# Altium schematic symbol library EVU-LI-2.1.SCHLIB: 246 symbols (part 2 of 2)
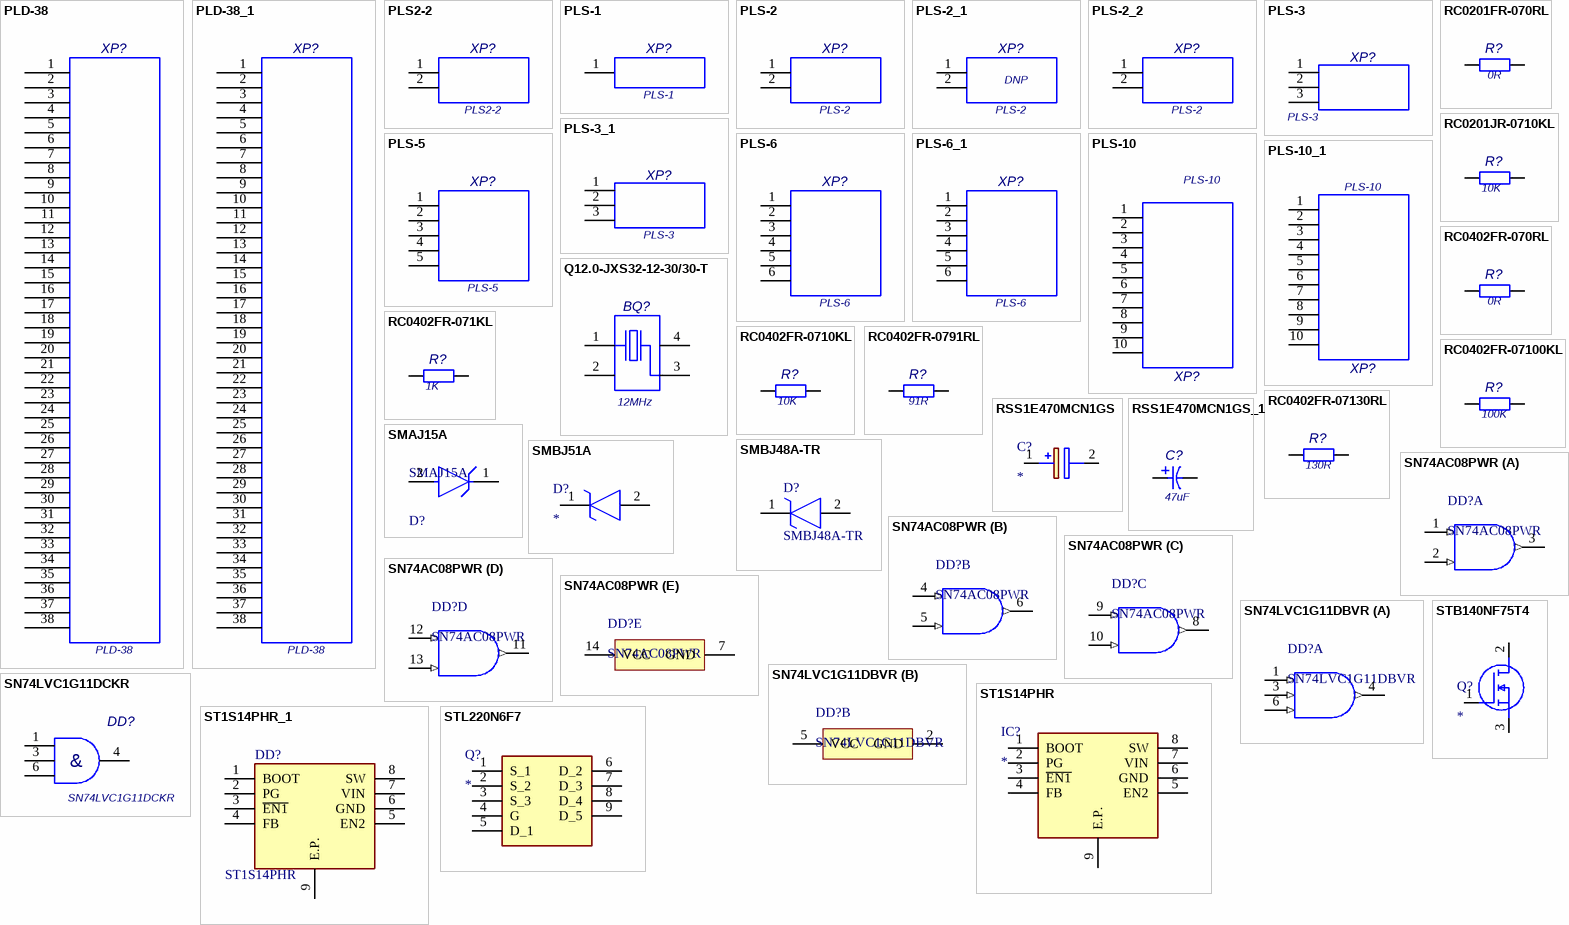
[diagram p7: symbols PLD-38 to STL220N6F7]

## PLS-10
designator XP?
2.54 pitch, 1 rows, 8.54 height; Manufacturer: "ТД Бурый медведь"
footprint PLS10-254PX254X25X854N
pins: 1, 2, 3, 4, 5, 6, 7, 8, 9, 10

## PLS-10_1
designator XP?, comment PLS-10
2.54 pitch, 1 rows, 8.54 height; Manufacturer: "ТД Бурый медведь"
footprint PLS10-254PX254X25X854N
pins: 1, 2, 3, 4, 5, 6, 7, 8, 9, 10

## Q12.0-JXS32-12-30/30-T
designator BQ?  value 12MHz  (hidden comment: Q12.0-JXS32-12-30/30-T)
Quartz Crystal 12MHz; Manufacturer: "Jauch"; ManufacturerPartNumber: Q12.0-JXS32-12-30/30-T1; MARK: ASFLK; Value Ru: 12,000 МГц
footprint JXS32X330X270X70N
pins: 1, 2, 3, 4

## RC0201FR-070RL
designator R?  value 0R  (hidden comment: RC0201FR-070RL)
0201 0 Ohm ±1% 0.05 W; Manufacturer: "Yageo"; Power_Voltage: 0,05 W; MARK: 000; TKE: 0402; NOM: 0402 0R ±1% 0,05 W; Value Ru: 0 Ом
footprint RES0201 (SMD Chip Resistor 0201,  metric 0603)
pins: 1, 2

## RC0201JR-0710KL
designator R?  value 10K  (hidden comment: RC0201JR-0710KL)
0201 10 kOhm ± 5% 0.05W; Manufacturer: "Yageo"; Power_Voltage: 0,05 W; MARK: 103; TKE: 0201; NOM: 0201 10K ±5% 0,05 W; Value Ru: 10 кОм
footprint RES0201 (SMD Chip Resistor 0201,  metric 0603)
pins: 1, 2

## RC0402FR-070RL
designator R?  value 0R  (hidden comment: RC0402FR-070RL)
0402 0 Ohm ±1% 0.063W; Manufacturer: "Yageo"; Power_Voltage: 0,0625 W; MARK: 000; TKE: 0402; NOM: 0402 0R ±1% 0,0625 W; Value Ru: 0 Ом
footprint RESC1005X35N
pins: 1, 2

## RC0402FR-071KL
designator R?  value 1K  (hidden comment: RC0402FR-071KL)
0402 1 kOhm ±1% 0.063W; Manufacturer: "Yageo"; Power_Voltage: 0,0625 W; MARK: 102; TKE: 0402; NOM: 0402 1K ±1% 0,0625 W; Value Ru: 1 кОм
footprint RESC1005X35N
pins: 1, 2

## RC0402FR-0710KL
designator R?  value 10K  (hidden comment: RC0402FR-0710KL)
0402 10 kOhm ±1% 0.063W; Manufacturer: "Yageo"; Power_Voltage: 0,0625 W; MARK: 103; TKE: 0402; NOM: 0402 10K ±1% 0,0625 W; Value Ru: 10 кОм
footprint RESC1005X35N
pins: 1, 2

## RC0402FR-0791RL
designator R?  value 91R  (hidden comment: RC0402FR-0791RL)
0402 91 Ohm ±1% 0.063W; Manufacturer: "Yageo"; Power_Voltage: 0,0625 W; MARK: 102; TKE: 0402; NOM: 0402 91R ±1% 0,0625 W; Value Ru: 91 Ом
footprint RESC1005X35N
pins: 1, 2

## RC0402FR-07100KL
designator R?  value 100K  (hidden comment: RC0402FR-07100KL)
0402 100 kOhm ±1% 0.063W; Manufacturer: "Yageo"; Power_Voltage: 0,0625 W; MARK: 103; TKE: 0402; NOM: 0402 100K ±1% 0,0625 W; Value Ru: 100 кОм
footprint RESC1005X35N
pins: 1, 2

## RC0402FR-07130RL
designator R?  value 130R  (hidden comment: RC0402FR-07130RL)
0402 130 Ohm ±1% 0.063W; Manufacturer: "Yageo"; Power_Voltage: 0,0625 W; MARK: 102; TKE: 0402; NOM: 0402 130R ±1% 0,0625 W; Value Ru: 130 Ом
footprint RESC1005X35N
pins: 1, 2

## RSS1E470MCN1GS
designator C?
Capacitor Polarised; Manufacturer_Name: Nichicon; Manufacturer_Part_Number: RSS1E470MCN1GS
footprint CAPAE650X600N
pins: 1 +, 2 -

## RSS1E470MCN1GS_1
designator C?, comment value 47uF  (hidden comment: RSS1E470MCN1GS)
47uF±20% 25V; Manufacturer: "Nichicon"; Tolerance: ±20%; Value Ru: 47 мкФ
footprint CAPAE650X600N
pins: 1, 2

## SMAJ15A
designator D?
TVS DIODE 15V 24.4V SMA; Manufacturer: "Bourns Inc."; Max Junction Temp: +150°C; Peak Pulse Current: 16.4A; Direction: Unidirectional; Breakdown Voltage: 16.7V; Number Of Channels: 1; Peak Pulse Power: 400W; TKE: SMA (DO-214AC)
footprint FP-SMA-MFG
pins: 1 C, 2 A

## SMBJ48A-TR
designator D?
TVS Diode (Uni-directional); Manufacturer_Name: STMicroelectronics; Manufacturer: "STMicroelectronics"; Power_Voltage: Vrm 48V, Irm 0.2A; TKE: SMB(DO-214AA-2)
footprint SMBJ12A
pins: 1 K, 2 A

## SMBJ51A
designator D?
TVS Diode (Uni-directional); Manufacturer_Name: LITTELFUSE; Manufacturer_Part_Number: SMBJ51A
footprint DIOM5436X261N
pins: 1 K, 2 A

## SN74AC08PWR
designator DD?
Quadruple 2-Input Positive-AND Gates, PW0014A, LARGE T&R; Manufacturer: "Texas Instruments"; Technology Family: AC; VCC(Min)(V): 2; Input Type: CMOS; Rating: Catalog; F @ Nom Voltage(Max)(Mhz): 100; Schmitt Trigger: No; Output Drive (IOL/IOH)(Max)(mA): -24/24; Bits(#): 4; Voltage(Nom)(V): 3.3,5; tpd @ Nom Voltage(Max)(ns): 10,8.5; VCC(Max)(V): 6; ICC @ Nom Voltage(Max)(mA): 0.02
footprint PW0014A_L (SOP, 14-Leads, Body 5.1x4.5mm, Pitch 0.65mm, IPC High Density)
footprint PW0014A_M (SOP, 14-Leads, Body 5.1x4.5mm, Pitch 0.65mm, IPC Low Density)
footprint PW0014A_N (SOP, 14-Leads, Body 5.1x4.5mm, Pitch 0.65mm, IPC Medium Density)
part A pins: 1 1A (in), 2 1B (in), 3 1Y (out)
part B pins: 4 2A (in), 5 2B (in), 6 2Y (out)
part C pins: 8 3Y (out), 9 3A (in), 10 3B (in)
part D pins: 11 4Y (out), 12 4A (in), 13 4B (in)
part E pins: 7 GND (power), 14 VCC (power)

## SN74LVC1G11DBVR
designator DD?
Single 3-Input Positive-AND Gate, DBV0006A, LARGE T&R; Manufacturer: Texas Instruments; Output Type: CMOS; Voltage(Nom)(V): 1.8,2.5,3.3,5; ICC @ Nom Voltage(Max)(mA): 0.01; VCC(Min)(V): 1.65; Output Drive (IOL/IOH)(Max)(mA): 32/-32; Schmitt Trigger: No; Input Type: CMOS/TTL; VCC(Max)(V): 5.5; Gate Type: AND; Rating: Catalog; tpd @ Nom Voltage(Max)(ns): 20,7.8,6.2,4.6; Bits(#): 1; F @ Nom Voltage(Max)(Mhz): 150; Logic: True; Technology Family: LVC
footprint DBV0006A_N (SOT23, 6-Leads, Body 3.05x1.75mm, Pitch 0.95mm, IPC Medium Density)
footprint DBV0006A_M (SOT23, 6-Leads, Body 3.05x1.75mm, Pitch 0.95mm, IPC Low Density)
footprint DBV0006A_L (SOT23, 6-Leads, Body 3.05x1.75mm, Pitch 0.95mm, IPC High Density)
part A pins: 1 A (in), 3 B (in), 4 Y (out), 6 C (in)
part B pins: 2 GND (power), 5 VCC (power)

## SN74LVC1G11DCKR
designator DD?
Single 3-Input Positive-AND Gate; Manufacturer: "Texas Instruments"
footprint SOT65P210X110-6N(SC70)
pins: 1 A, 3 B, 4 Y, 6 C

## ST1S14PHR
designator IC?
Integrated Circuit; Manufacturer_Name: STMicroelectronics; Manufacturer_Part_Number: ST1S14PHR
footprint SOIC127P600X175-9N
pins: 1 BOOT, 2 PG, 3 ~{EN1}, 4 FB, 5 EN2, 6 GND, 7 VIN, 8 SW, 9 E.P.

## ST1S14PHR_1
designator DD?, comment ST1S14PHR
DC-DC Step-Down; Manufacturer_Name: STMicroelectronics; Manufacturer: "STMicroelectronics"; TKE: HSOP-8
footprint SOIC127P600X175-9N
pins: 1 BOOT, 2 PG, 3 ~{EN1}, 4 FB, 5 EN2, 6 GND, 7 VIN, 8 SW, 9 E.P.

## STB140NF75T4
designator Q?
MOSFET (N-Channel); Manufacturer_Name: STMicroelectronics; Manufacturer_Part_Number: STB140NF75T4
footprint STB120N4F6
pins: 1 G, 2 D, 3 S

## STL220N6F7
designator Q?
MOSFET (N-Channel); Manufacturer_Name: STMicroelectronics; Manufacturer_Part_Number: STL220N6F7
footprint FERD20U50DJFTR
pins: 1 S_1, 2 S_2, 3 S_3, 4 G, 5 D_1, 6 D_2, 7 D_3, 8 D_4, 9 D_5

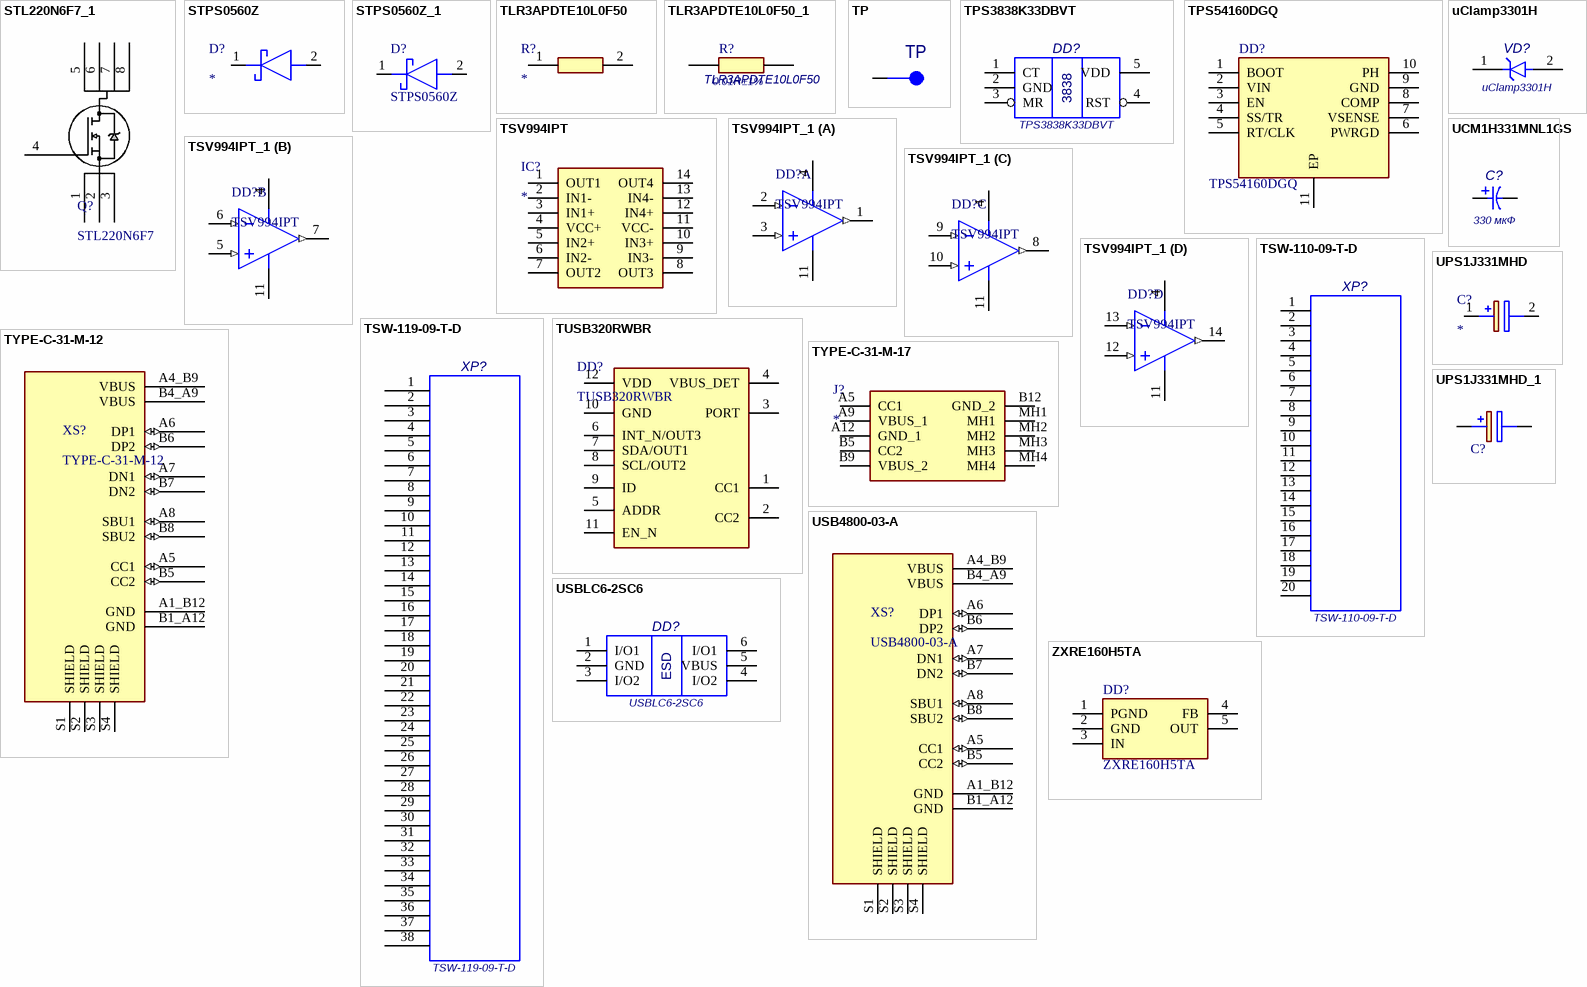
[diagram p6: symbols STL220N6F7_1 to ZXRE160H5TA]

## STL220N6F7_1
designator Q?, comment STL220N6F7
N-channel 60 V, 1.2 mΩ typ., 120 A STripFET; Mfr_Name: STMicroelectronics; Manufacturer: "STMicroelectronics"; TKE: 8-PowerVDFN
footprint FERD20U50DJFTR
pins: 1 S, 2 S, 3 S, 4 G, 5 D, 6 D, 7 D, 8 D

## STPS0560Z
designator D?
Schottky Diode; Manufacturer_Name: STMicroelectronics; Manufacturer_Part_Number: STPS0560Z
footprint STPS0560Z
pins: 1 K, 2 A

## STPS0560Z_1
designator D?, comment STPS0560Z
Schottky Diode; Manufacturer_Name: STMicroelectronics; Manufacturer: "STMicroelectronics"; TKE: SOD-123; Pover_Voltage: Vf 0.5V Vrrm60V If 0.5A
footprint STPS0560Z
pins: 1 K, 2 A

## TLR3APDTE10L0F50
designator R?
Resistor; Manufacturer_Name: KOA Speer; Manufacturer_Part_Number: TLR3APDTE10L0F50
footprint RESC6432X87N
pins: 1, 2

## TLR3APDTE10L0F50_1
designator R?, comment TLR3APDTE10L0F50  value 0.01R  Tolerance: ±1%
Current Sense Resistor  2512 10 mOhms±1% 3W; Manufacturer: "KOA Speer"; TKE: 2512; Value Ru: 0.01 Ом
footprint RESC6432X87N
pins: 1, 2

## TP
designator TP  (no BOM)
Contacts, Test points and mounting hole pin
footprint PIN_0.7x0.7
footprint PIN_0.7x0.7
pins: 1

## TPS3838K33DBVT
designator DD?
Supervisor Integrated Circuit; Manufacturer: "Texas Instruments"
footprint SOT95P280X145-5N
pins: 1 CT, 2 GND, 3 MR, 4 RST, 5 VDD

## TPS54160DGQ
designator DD?
DC-DC STEP DOWN Converter 1.5-A, 60V; Manufacturer: "Texas Instruments"
footprint SOP50P490X110-11N
pins: 1 BOOT, 2 VIN, 3 EN, 4 SS/TR, 5 RT/CLK, 6 PWRGD, 7 VSENSE, 8 COMP, 9 GND, 10 PH, 11 EP

## TSV994IPT
designator IC?
Integrated Circuit; Manufacturer_Name: STMicroelectronics; Manufacturer_Part_Number: TSV994IPT
footprint SOP65P640X120-14N
pins: 1 OUT1, 2 IN1-, 3 IN1+, 4 VCC+, 5 IN2+, 6 IN2-, 7 OUT2, 8 OUT3, 9 IN3-, 10 IN3+, 11 VCC-, 12 IN4+, 13 IN4-, 14 OUT4

## TSV994IPT_1
designator DD?, comment TSV994IPT
Comparator, TSSOP-14; Manufacturer: "Texas Instruments"; PowerWise: Y
footprint SOP65P640X120-14N
pins on every part: 4 VCC+ (power), 11 VCC- (power)
part A pins: 1 OUT1 (out), 2 IN1- (in), 3 IN1+ (in)
part B pins: 5 IN2+ (in), 6 IN2- (in), 7 OUT2 (out)
part C pins: 8 OUT3 (out), 9 IN3- (in), 10 IN3+ (in)
part D pins: 12 IN4+ (in), 13 IN4- (in), 14 OUT4 (out)

## TSW-110-09-T-D
designator XP?
Connector 2.54 pitch, 2 rows; Manufacturer: "Samtec"
footprint PLD20-254PX2548X254X854N
pins: 1, 2, 3, 4, 5, 6, 7, 8, 9, 10, 11, 12, 13, 14, 15, 16, 17, 18, 19, 20

## TSW-119-09-T-D
designator XP?
Connector 2.54 pitch, 2 rows; Manufacturer: "Samtec"
footprint PLD38-254PX4834X254X854N
pins: 1, 2, 3, 4, 5, 6, 7, 8, 9, 10, 11, 12, 13, 14, 15, 16, 17, 18, 19, 20, 21, 22, 23, 24, 25, 26, 27, 28, 29, 30, 31, 32, 33, 34, 35, 36, 37, 38

## TUSB320RWBR
designator DD?
USB Type-C Logic & Port Control; Manufacturer: "Texas Instruments"
footprint TUSB320RWBR
pins: 1 CC1, 2 CC2, 3 PORT, 4 VBUS_DET, 5 ADDR, 6 INT_N/OUT3, 7 SDA/OUT1, 8 SCL/OUT2, 9 ID, 10 GND, 11 EN_N, 12 VDD

## TYPE-C-31-M-12
designator XS?
USB TYPE-C 5A 16P Female SMD USB Connectors; Manufacturer: "GCT"; MP: USB4800-03-A; MF: Global Connector Technology
footprint TYPE-C-31-M-12 (USB TYPE-C 5A 16P Female SMD USB Connectors)
pins: A1_B12 GND (power), A4_B9 VBUS (power), A5 CC1 (io), A6 DP1 (io), A7 DN1 (io), A8 SBU1 (io), B1_A12 GND (power), B4_A9 VBUS (power), B5 CC2 (io), B6 DP2 (io), B7 DN2 (io), B8 SBU2 (io), S1 SHIELD, S2 SHIELD, S3 SHIELD, S4 SHIELD

## TYPE-C-31-M-17
designator J?
Connector; Manufacturer_Name: Korean Hroparts Elec; Manufacturer_Part_Number: TYPE-C-31-M-17
footprint TYPEC31M17
pins: A5 CC1, A9 VBUS_1, A12 GND_1, B5 CC2, B9 VBUS_2, B12 GND_2, MH1, MH2, MH3, MH4

## uClamp3301H
designator VD?
Manufacturer: "Semtech"; MARK: 3H
footprint SOD523X170X90X700
pins: 1 C, 2 A

## UCM1H331MNL1GS
designator C?  value 330 мкФ  (hidden comment: UCM1H331MNL1GS)
330 мкФ ±20% 50B; Manufacturer: "Nichicon"
footprint CAP_CXUD100X100_NICHICON (Footprint not found)
pins: 1, 2

## UPS1J331MHD
designator C?
Capacitor Polarised; Manufacturer_Name: Nichicon; Manufacturer_Part_Number: UPS1J331MHD
footprint CAPPRD500W60D1275H2200
pins: 1 +, 2 -

## UPS1J331MHD_1
designator C?, comment UPS1J331MHD  (value not drawn)
Capacitor Polarised; Manufacturer_Name: Nichicon
footprint CAPPRD500W60D1275H2200
pins: 1 +, 2 -

## USB4800-03-A
designator XS?
USB-C (USB TYPE-C) USB 2.0 Receptacle Connector 24 (16+8 Dummy) Position Surface Mount, Right Angle; Through Hole; Manufacturer: "GCT"; MF: Global Connector Technology
footprint GCT_USB4800-03-A_REVA
pins: A1_B12 GND (power), A4_B9 VBUS (power), A5 CC1 (io), A6 DP1 (io), A7 DN1 (io), A8 SBU1 (io), B1_A12 GND (power), B4_A9 VBUS (power), B5 CC2 (io), B6 DP2 (io), B7 DN2 (io), B8 SBU2 (io), S1 SHIELD, S2 SHIELD, S3 SHIELD, S4 SHIELD

## USBLC6-2SC6
designator DD?
Very low capacitance ESD protector; Manufacturer: "STMicroelectronics"; MARK: UL26
footprint SOT95P280X145-6N
pins: 1 I/O1, 2 GND, 3 I/O2, 4 I/O2, 5 VBUS, 6 I/O1

## ZXRE160H5TA
designator DD?
V-Ref Adjustable 0.2V to 18V 15mA; Manufacturer: "Diodes Incorporated"; TKE: SOT-353
footprint SOT65P210X110-5N
pins: 1 PGND, 2 GND, 3 IN, 4 FB, 5 OUT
